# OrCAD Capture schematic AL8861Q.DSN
size Custom; title: AL8861Q, 40V 1.5A Automotive Grade Buck LED Driver; rev: 1.4; note: DS41798 Rev. 3 - 2
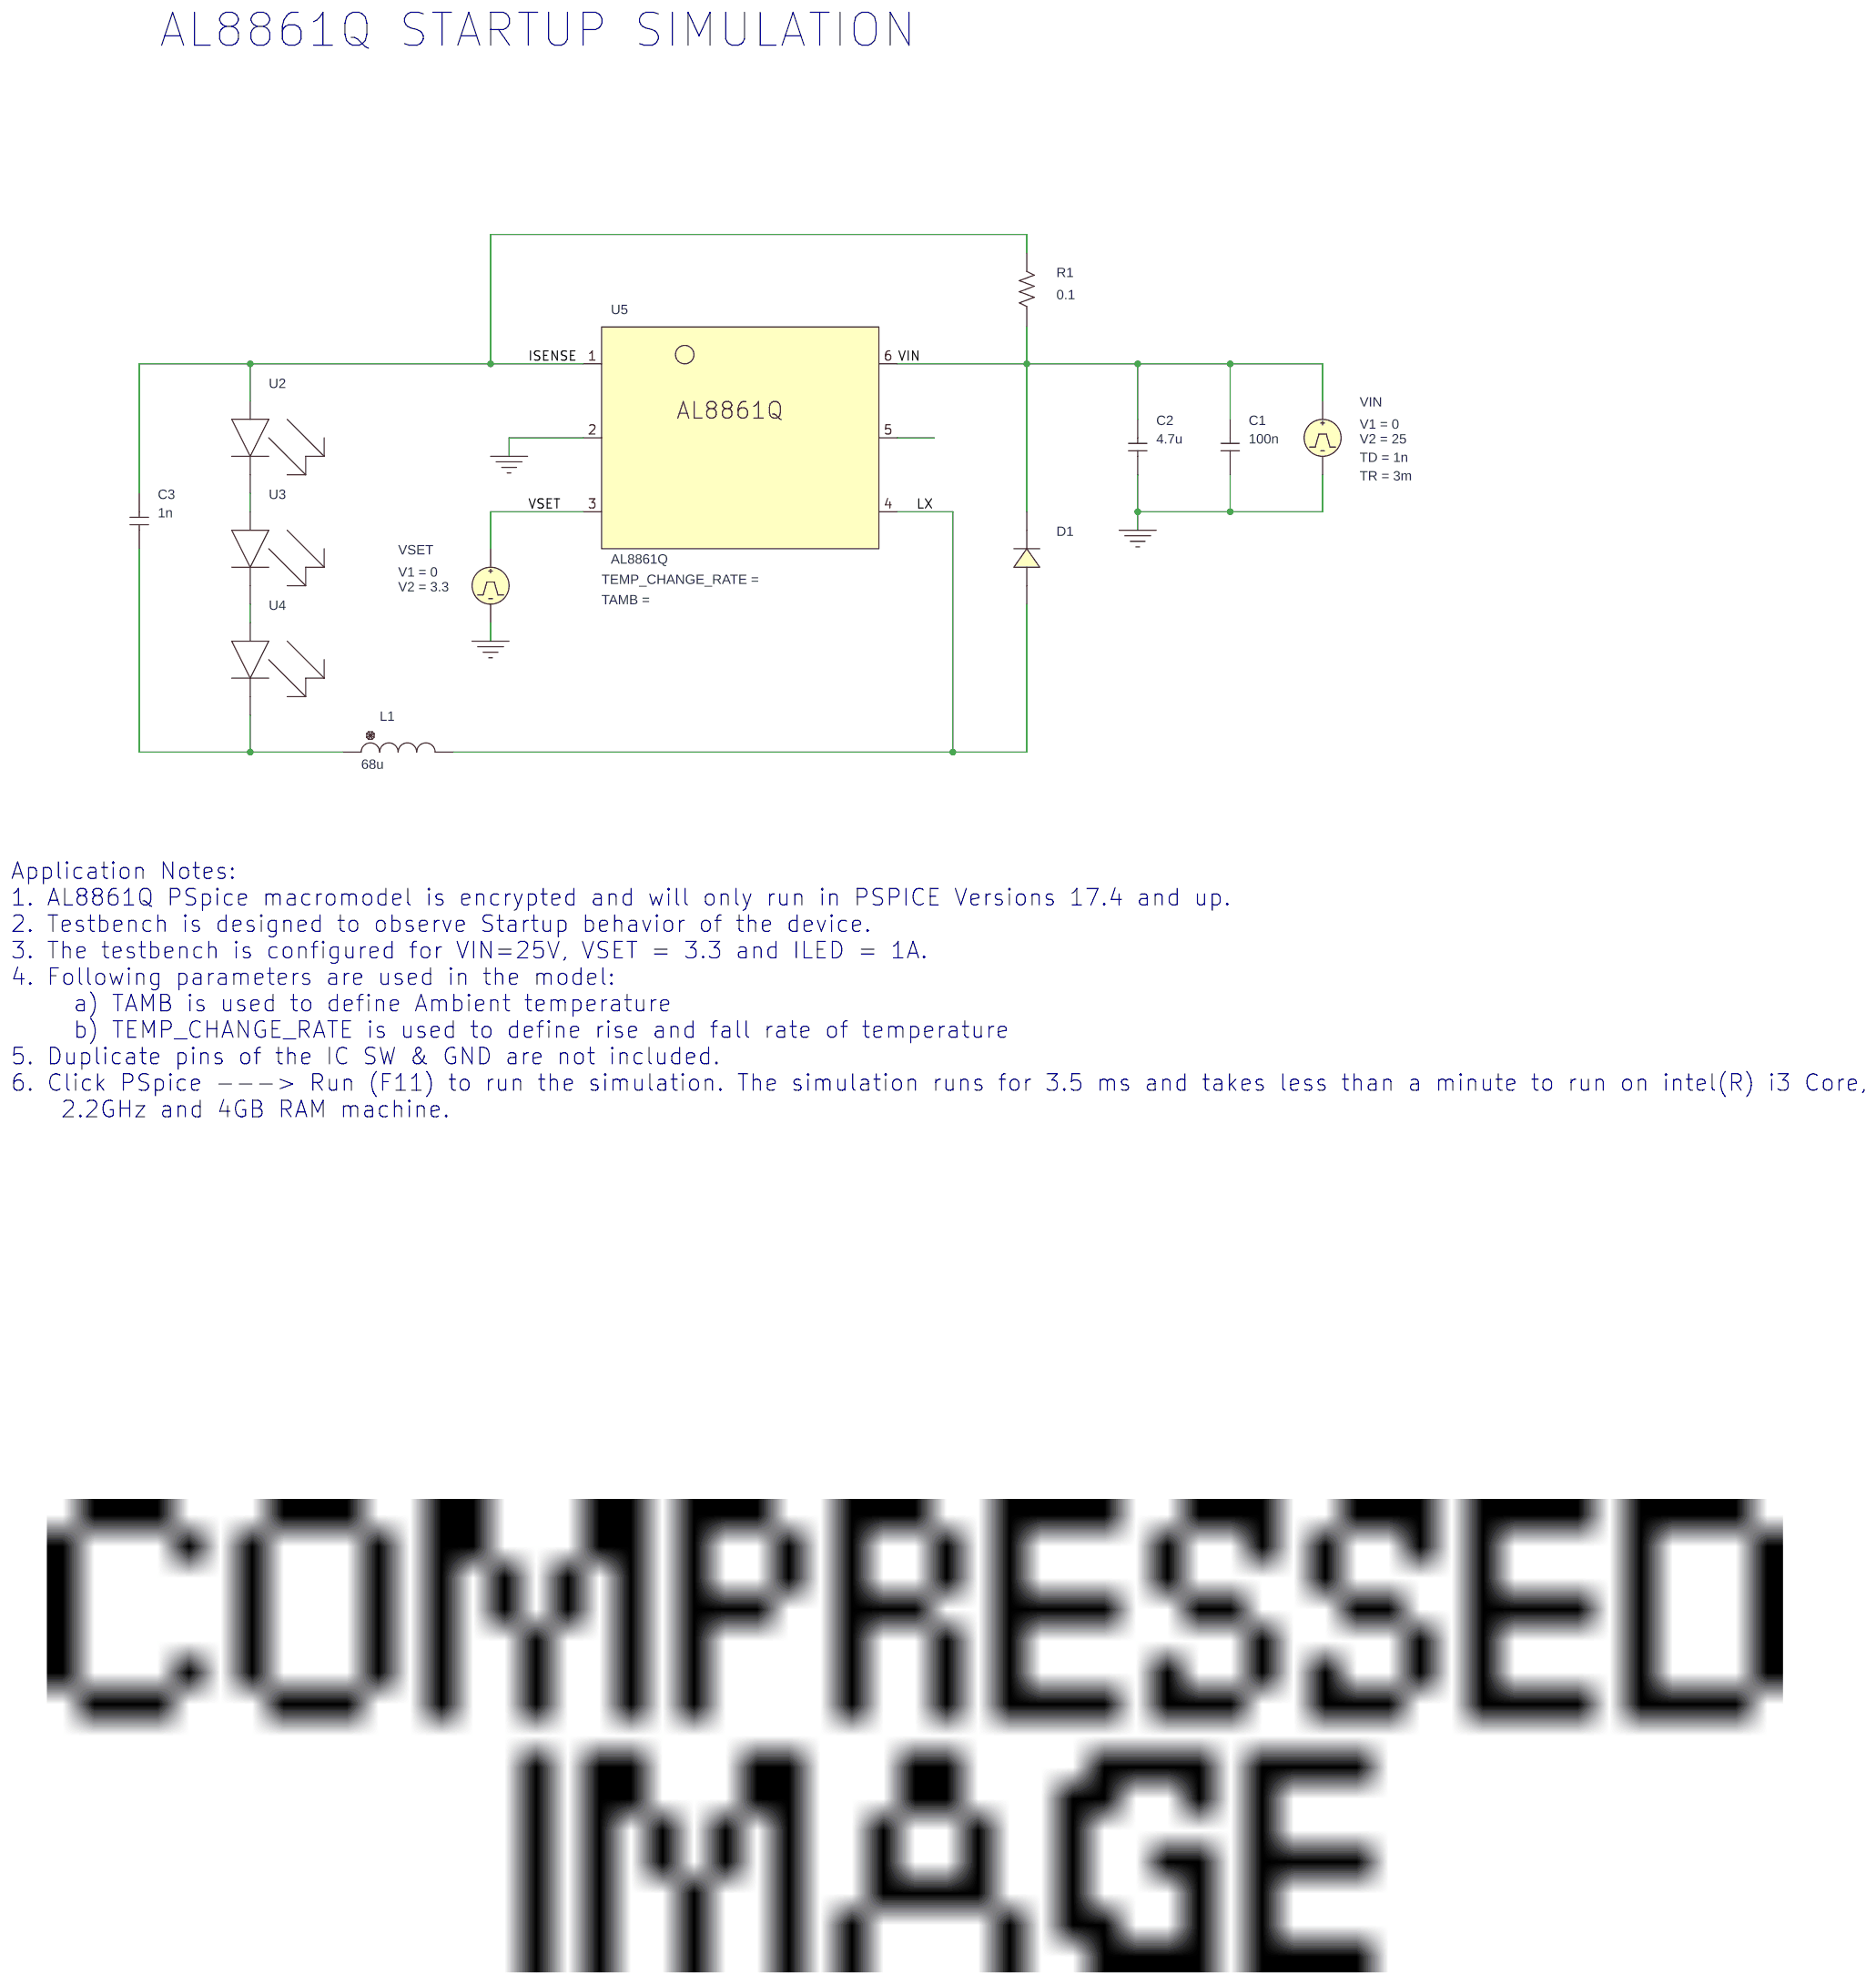
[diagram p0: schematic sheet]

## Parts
C1  100n  [RAD/CK05]
C2  4.7u  [RAD/CK05]
C3  1n  [RAD/CK05]
D1  B240A
L1  68u  [DISC/.350x.175/LS.200x.100/.034]
R1  0.1  [AX/RC05]
U2  _D2_mod
U3  _D2_mod
U4  _D2_mod
U5  AL8861Q
VIN  VPULSE
VSET  VPULSE

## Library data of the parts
C1-C3 = C
D1 = B240A
L1 = L: IC: 0
R1 = R
U2-U4 = LEDR
U5 = AL8861Q
VIN = VPULSE: TD: 1n; TR: 3m; V1: 0; V2: 25
VSET = VPULSE: V1: 0; V2: 3.3

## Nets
VIN: C1.2 C2.2 D1.1(C) R1.1 U5.6(VIN) VIN.1(+)
0: C1.1 C2.1 U5.2(GND) VIN.2(-) VSET.2(-)
ISENSE: C3.2 R1.2 U2.1(A) U5.1(ISENSE)
LX: D1.2(A) L1.2 U5.4(LX)
VSET: U5.3(VSET) VSET.1(+)
N00798: U2.2(C) U3.1(A)
N00908: C3.1 L1.1 U4.2(C)
N00948: U3.2(C) U4.1(A)

Not connected (* = marked no-connect by the designer): U5 5(N/C)

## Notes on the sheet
- AL8861Q STARTUP SIMULATION
- Application Notes:
  1. AL8861Q PSpice macromodel is encrypted and will only run in PSPICE Versions 17.4 and up.
  2. Testbench is designed to observe Startup behavior of the device.
  3. The testbench is configured for VIN=25V, VSET = 3.3 and ILED = 1A.
  4. Following parameters are used in the model:
       a) TAMB is used to define Ambient temperature
       b) TEMP_CHANGE_RATE is used to define rise and fall rate of temperature
  5. Duplicate pins of the IC SW & GND are not included.
  6. Click PSpice ---> Run (F11) to run the simulation. The simulation runs for 3.5 ms and takes less than a minute to run on intel(R) i3 Core,
      2.2GHz and 4GB RAM machine.
